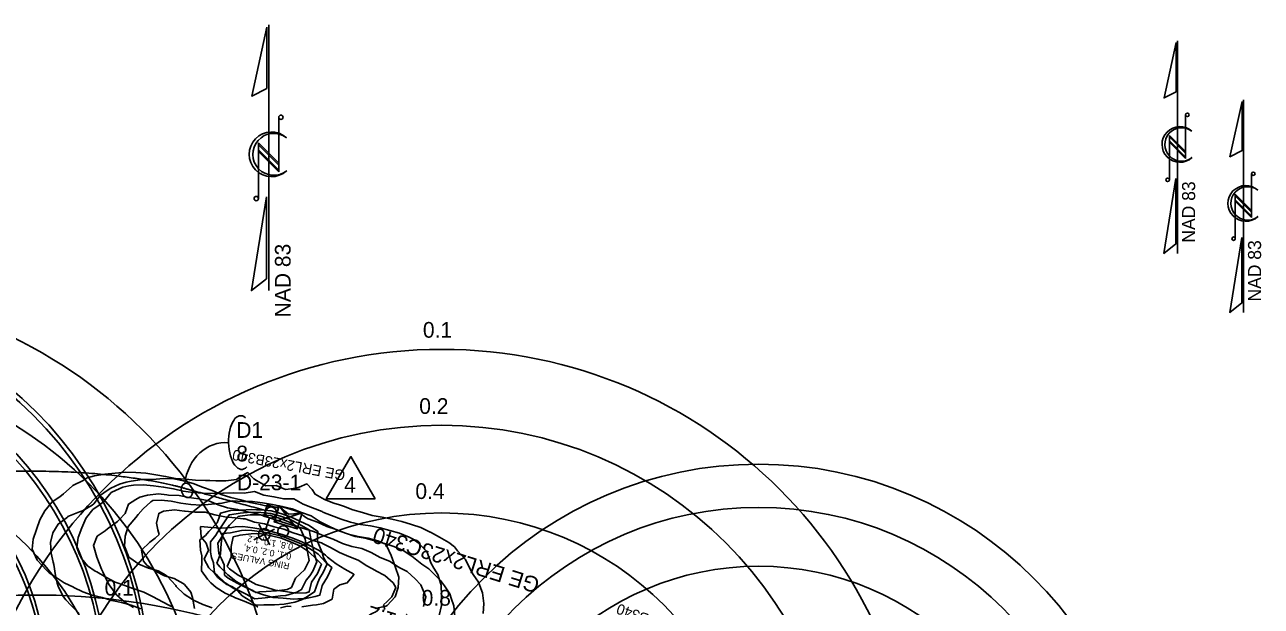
# Model space of a CAD drawing. Extents: x 1638506 to 1658005, y 834807 to 846788.
# Drawn here: x 1641220 to 1642165, y 842638 to 843083 of the extents above; entities that cross this region are included whole.
import ezdxf

# ---------------------------------------------------------------- set-up
doc = ezdxf.new("R2010")
doc.units = 0
for name, color, linetype in [('Default', 7, 'Continuous'), ('Old_Level_1', 7, 'Continuous'), ('Old_Level_2', 7, 'Continuous'), ('Old_Level_4', 7, 'Continuous'), ('Scratch_Level_0', 7, 'Continuous'), ('Sheet North Arrow CELL', 7, 'Continuous')]:
    doc.layers.add(name, color=color, linetype=linetype)

msp = doc.modelspace()

# ---------------------------------------------------------------- linework, layer by layer
at = {"layer": 'Default'}
for p, q in [((1641428.42, 842697.5), (1641414.73, 842715.25)), ((1641407.25, 842706.1), (1641404.63, 842697.54)), ((1641432.21, 842709.89), (1641410.93, 842702.85)), ((1641411.2, 842697.47), (1641395.43, 842689.09)), ((1641407.53, 842685.39), (1641399.12, 842701.17)), ((1641403.32, 842693.26), (1641403.32, 842693.26)), ((1641407.31, 842695.4), (1641407.31, 842695.4))]:
    msp.add_line(p, q, dxfattribs=at)
for points in [[(1641488.06, 842720.59), (1641450.67, 842720.59), (1641469.5, 842752.86)], [(1641414.13, 842713.31), (1641411.53, 842704.79), (1641402.97, 842707.4), (1641405.58, 842715.93)], [(1641432.21, 842709.89), (1641414.73, 842715.25), (1641410.93, 842702.85), (1641428.42, 842697.5)], [(1641421.57, 842706.37), (1641410.93, 842702.85), (1641414.73, 842715.25)], [(1641421.57, 842706.37), (1641428.42, 842697.5), (1641432.21, 842709.89)]]:
    msp.add_lwpolyline(points, close=True, dxfattribs=at)
msp.add_circle((1641403.32, 842693.3), 4.47, dxfattribs=at)
for centre, major_axis, ratio, start_param, end_param in [((1641385.66, 842763.53), (-0.49, 20.52), 0.466223, 5.884886, 7.853982), ((1641372.31, 842728.96), (-3.78, -34.34), 0.862742, 3.141593, 4.712389), ((1641385.66, 842763.53), (-0.49, 20.52), 0.466223, 1.570796, 3.572354)]:
    msp.add_ellipse(centre, major_axis=major_axis, ratio=ratio, start_param=start_param, end_param=end_param, dxfattribs=at)
msp.add_ellipse((1641344.25, 842726.93), major_axis=(1.72, -5.4), ratio=0.730797, dxfattribs=at)
msp.add_open_spline([(1641118.5, 842733.75), (1641184.14, 842741.69), (1641261.51, 842741.69), (1641322.44, 842734.15), (1641359.07, 842723.88), (1641404.28, 842711.67)], degree=2, dxfattribs=at)
at = {"layer": 'Old_Level_1'}
for points in [[(1641570.58, 842632.92), (1641570.95, 842640.63), (1641569.9, 842648.61), (1641568.78, 842652.1), (1641567.04, 842656.93), (1641563, 842662.76), (1641561.18, 842665.82), (1641557.27, 842673.69), (1641556.89, 842674.41), (1641550.81, 842680.74), (1641548.72, 842683.73), (1641544.25, 842687.24), (1641537.23, 842691.32), (1641530.2, 842694.99), (1641530.14, 842695.02), (1641523.04, 842698.63), (1641515.7, 842700.99), (1641508.35, 842703.31), (1641500.89, 842705.05), (1641493.38, 842706.5), (1641485.84, 842707.77), (1641478.47, 842710.01), (1641471.08, 842712.06), (1641463.82, 842714.85), (1641460.81, 842715.82), (1641456.49, 842717.28), (1641449.23, 842720.05), (1641442.2, 842724.08), (1641439.91, 842727.53), (1641435.92, 842732.07), (1641429.99, 842729.39), (1641427.51, 842728.78), (1641419.52, 842727.65), (1641412.31, 842730.72), (1641404.48, 842730.47), (1641397.44, 842734.43), (1641395.35, 842735.9), (1641390.81, 842740.54), (1641385.44, 842737.77), (1641382.05, 842735.38), (1641374.04, 842734.18), (1641366.27, 842734.24), (1641361.71, 842734.44), (1641358.56, 842734.64), (1641350.78, 842734.67), (1641343.14, 842735.44), (1641335.47, 842736.03), (1641327.98, 842737.59), (1641320.45, 842738.96), (1641312.87, 842740.05), (1641305.18, 842740.55), (1641297.49, 842741.02), (1641289.56, 842740.24), (1641289.5, 842740.23), (1641281.61, 842739.36), (1641273.59, 842738.11), (1641268.15, 842736.46), (1641265.11, 842734.43), (1641257.15, 842730.74), (1641256.54, 842730.21), (1641250.04, 842724.3), (1641247.23, 842722.11), (1641241.35, 842718.15), (1641237.97, 842714.28), (1641235.66, 842711.43), (1641231.79, 842704.37), (1641229.33, 842697.05), (1641226.71, 842689.76), (1641226.02, 842682.11), (1641229.92, 842673.59)], [(1641536.84, 842631.47), (1641538.72, 842638.9), (1641538.72, 842646.69), (1641538.45, 842654.52), (1641538.24, 842655.28), (1641535.91, 842662.78), (1641532.77, 842667.57), (1641530.49, 842671.59), (1641527.77, 842679.88), (1641527.38, 842680.32), (1641520.86, 842687.02), (1641516.96, 842689.7), (1641513.88, 842691.31), (1641506.68, 842694.41), (1641499.28, 842696.45), (1641491.86, 842698.41), (1641484.35, 842699.83), (1641476.77, 842700.95), (1641469.31, 842702.67), (1641461.95, 842704.95), (1641454.7, 842707.75), (1641448.13, 842710.42), (1641447.48, 842710.78), (1641440.25, 842713.72), (1641432.98, 842716.46), (1641425.94, 842720.4), (1641418.16, 842720.43), (1641410.7, 842722.13), (1641403.12, 842723.26), (1641395.87, 842726.05), (1641387.87, 842724.94), (1641380.1, 842725.02), (1641372.3, 842724.91), (1641371.56, 842724.81), (1641364.48, 842724.7), (1641356.7, 842724.73), (1641349.02, 842725.28), (1641341.44, 842726.39), (1641333.98, 842728.09), (1641326.46, 842729.49), (1641318.84, 842730.36), (1641311.2, 842731.15), (1641303.36, 842730.87), (1641299.91, 842730.49), (1641295.31, 842729.41), (1641286.79, 842725.54), (1641286.27, 842725.27), (1641280.73, 842718.53), (1641277.15, 842715.62), (1641272.48, 842712.3), (1641267.58, 842706.15), (1641267.11, 842705.52), (1641264.02, 842698.32), (1641261.19, 842691.07), (1641260.25, 842683.46)], [(1641488.06, 842636.77), (1641496.2, 842638.63), (1641497.14, 842638.94), (1641503.39, 842645.54), (1641505.71, 842652.89), (1641506.08, 842660.61), (1641503.27, 842668.92), (1641502.41, 842671.72), (1641500.3, 842677.26), (1641497.01, 842684.36), (1641495.93, 842685.87), (1641489.99, 842688.42), (1641482.58, 842690.45), (1641475.04, 842691.73), (1641467.6, 842693.57), (1641460.28, 842696.01), (1641453.14, 842699.44), (1641446.02, 842702.99), (1641445.9, 842703.05), (1641439.1, 842707.61), (1641431.77, 842710.01), (1641424.53, 842712.87), (1641417.08, 842714.69), (1641409.6, 842716.27), (1641402.05, 842717.52), (1641394.45, 842718.53), (1641386.66, 842718.49), (1641378.96, 842718.92), (1641370.97, 842717.14), (1641370.83, 842717.12), (1641362.92, 842716.4), (1641355.02, 842715.79), (1641347.31, 842716.18), (1641339.71, 842717.16), (1641332.22, 842718.72), (1641324.58, 842719.51), (1641318.12, 842719.29), (1641316.57, 842718.28), (1641310.92, 842712.85), (1641306.94, 842708.46), (1641305.12, 842706.16), (1641299.48, 842699.44), (1641297.03, 842692.11), (1641296.52, 842684.42), (1641299.95, 842676)], [(1641354.67, 842681.28), (1641355.52, 842677.06), (1641355.74, 842673.29), (1641355.42, 842665.57), (1641359.95, 842659.18), (1641362.4, 842656.47), (1641366.54, 842652.87), (1641373.52, 842648.55), (1641380.35, 842645.32), (1641380.67, 842645.18), (1641387.94, 842642.44), (1641395.14, 842639.35), (1641402.97, 842639.61), (1641410.74, 842639.53), (1641411.08, 842639.54), (1641418.63, 842640.07), (1641426.69, 842641.56), (1641431.86, 842643.42), (1641435.13, 842645.05), (1641441.66, 842649.36), (1641444.17, 842656.67), (1641445.74, 842660.1), (1641448.07, 842663.73), (1641451.46, 842670.87), (1641448.66, 842675.65), (1641447.47, 842679.41), (1641443.94, 842687.85), (1641444, 842692.22), (1641444.18, 842695.59), (1641437.72, 842700.23), (1641430.54, 842703.47), (1641423.38, 842706.77), (1641419.48, 842708.02), (1641416.06, 842709.27), (1641408.67, 842711.34), (1641401.03, 842712.09), (1641397.39, 842712.17), (1641393.3, 842712.42), (1641385.43, 842711.95), (1641377.57, 842711.53), (1641369.86, 842709.56), (1641368.81, 842706.35), (1641367.28, 842702.26), (1641360.92, 842695.67), (1641358.44, 842692.6), (1641354.1, 842689.17), (1641354.67, 842681.28)], [(1641362.26, 842679.85), (1641363.06, 842675.76), (1641364.54, 842671.64), (1641365.24, 842663.72), (1641367.96, 842660.39), (1641374.75, 842655.14), (1641378.54, 842653.44), (1641381.87, 842651.6), (1641388.95, 842647.84), (1641396.03, 842644.07), (1641403.99, 842645.01), (1641411.95, 842645.95), (1641415.72, 842646.45), (1641419.86, 842646.66), (1641428.1, 842649.09), (1641431.85, 842651.21), (1641435.37, 842658.33), (1641438.25, 842661.63), (1641440.48, 842665.15), (1641443.41, 842672.39), (1641441.46, 842678.71), (1641441.1, 842680.6), (1641439.19, 842688.75), (1641437.5, 842696.85), (1641437.13, 842697.11), (1641430.09, 842701.09), (1641422.99, 842704.71), (1641415.7, 842707.32), (1641408.29, 842709.32), (1641400.66, 842710.15), (1641392.92, 842710.36), (1641384.98, 842709.57), (1641376.98, 842708.42), (1641376.54, 842708.3), (1641372.03, 842701.37), (1641367.29, 842694.48), (1641366.27, 842692.84), (1641362.16, 842687.66), (1641362.26, 842679.85)], [(1641368.65, 842678.65), (1641370.62, 842674.57), (1641372.61, 842670.12), (1641373, 842662.27), (1641375.63, 842659.82), (1641382.7, 842655.99), (1641389.85, 842652.62), (1641394.54, 842650.43), (1641396.95, 842649.01), (1641399.72, 842649.46), (1641404.88, 842649.79), (1641412.77, 842650.34), (1641420.74, 842651.34), (1641424.08, 842652.67), (1641427.3, 842659.84), (1641430.77, 842663.26), (1641434.09, 842666.35), (1641437.71, 842673.46), (1641436.11, 842681.54), (1641435.19, 842686.78), (1641434.52, 842689.62), (1641430.68, 842698.13), (1641429.65, 842698.72), (1641422.6, 842702.65), (1641415.37, 842705.59), (1641408, 842707.76), (1641400.34, 842708.41), (1641392.53, 842708.31), (1641384.54, 842707.2), (1641383.37, 842707.02), (1641376.7, 842700.49), (1641375.04, 842698.09), (1641372.28, 842693.54), (1641367.86, 842686.59), (1641368.65, 842678.65)], [(1641260.25, 842683.46), (1641262.3, 842678.06), (1641263.62, 842675.04), (1641268.43, 842669.26), (1641274.21, 842665.27), (1641275.35, 842664.63), (1641282.38, 842660.66), (1641289.45, 842656.84), (1641296.74, 842654.23), (1641303, 842652.07), (1641304.05, 842651.68), (1641311.35, 842649.12), (1641318.47, 842645.56), (1641325.53, 842641.72), (1641331.06, 842639.01), (1641332.64, 842638.12)], [(1641229.92, 842673.59), (1641230.26, 842673.21), (1641236.73, 842666.23), (1641239.01, 842664.1), (1641243.5, 842660.82), (1641250.45, 842656.42), (1641257.59, 842652.96), (1641257.99, 842652.75), (1641264.72, 842649.48), (1641272, 842646.85), (1641279.46, 842645.09), (1641286.84, 842642.96), (1641294.32, 842641.35), (1641301.7, 842639.16), (1641308.99, 842636.54)], [(1641299.95, 842676), (1641300.72, 842675.37), (1641307.62, 842670.68), (1641314.82, 842667.58), (1641322.2, 842665.43), (1641326.49, 842663.22), (1641329.22, 842661.37), (1641335.67, 842654.28), (1641336.09, 842653.64), (1641342.23, 842647.77), (1641348.63, 842643.5), (1641349.16, 842643.22), (1641356.29, 842639.72), (1641363.61, 842637.25)]]:
    msp.add_lwpolyline(points, dxfattribs=at)
for centre, radius in [((1641016.92, 842574.38), 297), ((1641016.92, 842574.38), 264), ((1641016.92, 842574.38), 219), ((1641408.43, 842710.09), 4.21)]:
    msp.add_circle(centre, radius, dxfattribs=at)
at = {"layer": 'Old_Level_2'}
msp.add_arc((1641228.74, 842129.06), 518, 64.83812, 98.96792, dxfattribs=at)
at = {"layer": 'Old_Level_4'}
for centre, radius in [((1641051.91, 842515.45), 365), ((1641538.84, 842469.72), 365), ((1641051.91, 842515.45), 307), ((1641538.84, 842469.72), 307), ((1641051.91, 842515.45), 240), ((1641538.84, 842469.72), 240)]:
    msp.add_circle(centre, radius, dxfattribs=at)
at = {"layer": 'Scratch_Level_0'}
for points in [[(1641548.87, 842630.67), (1641548.24, 842638.89), (1641546.17, 842644.74), (1641545.02, 842647.91), (1641541.09, 842654.11), (1641537.9, 842658.14), (1641535.22, 842660.99), (1641529.06, 842666.93), (1641523.68, 842670.6), (1641522.48, 842671.52), (1641516.1, 842676.73), (1641509.42, 842681.01), (1641502.4, 842684.21), (1641495.1, 842686.5), (1641487.68, 842688.4), (1641480.31, 842690.44), (1641472.71, 842691.77), (1641465.47, 842694.25), (1641458.33, 842697.06), (1641451.05, 842699.42), (1641444.04, 842702.62), (1641436.85, 842705.26), (1641435.15, 842706.27), (1641430.29, 842709.94), (1641425.95, 842709.15), (1641421.94, 842708.85), (1641418.81, 842711.37), (1641415.69, 842714.5), (1641409.61, 842714.25), (1641407.64, 842714.39), (1641400.22, 842716.31), (1641392.64, 842717.67), (1641385.31, 842719.87), (1641377.84, 842721.63), (1641370.48, 842723.71), (1641363.47, 842726.94), (1641356.25, 842729.46), (1641349.06, 842732.12), (1641341.76, 842734.4), (1641334.17, 842735.76), (1641326.24, 842736.04), (1641318.03, 842735.39), (1641316.52, 842735.31), (1641310, 842735.36), (1641301.56, 842733.98), (1641297.73, 842733.17), (1641292.82, 842731.66), (1641286.06, 842728.8), (1641283.3, 842726.85), (1641278.27, 842723.22), (1641273.08, 842716.82), (1641271.81, 842715.71), (1641264.56, 842711.47), (1641262.16, 842710.48), (1641253.35, 842706.96), (1641252.94, 842706.64), (1641245.98, 842701.25), (1641241.89, 842694.51), (1641239.98, 842687.09), (1641240.58, 842678.89)], [(1641524.94, 842638.15), (1641526.78, 842645.59), (1641524.31, 842651.71), (1641522.85, 842654.83), (1641518.7, 842659.41), (1641512.42, 842664.95), (1641506.83, 842667.85), (1641505.55, 842668.63), (1641498.87, 842672.89), (1641491.77, 842675.81), (1641484.9, 842679.49), (1641477.82, 842682.47), (1641470.29, 842684.04), (1641462.99, 842686.31), (1641456.01, 842689.64), (1641448.85, 842692.38), (1641441.77, 842695.36), (1641434.43, 842697.53), (1641427.07, 842699.62), (1641419.75, 842701.84), (1641412.47, 842704.18), (1641405.22, 842706.65), (1641397.96, 842709.04), (1641390.44, 842710.63), (1641382.99, 842712.45), (1641375.36, 842713.68), (1641368.06, 842715.97), (1641360.98, 842718.97), (1641353.46, 842720.55), (1641345.73, 842721.43), (1641338.22, 842723.07), (1641330.3, 842723.37), (1641328.8, 842723.46), (1641322.56, 842724.26), (1641314.24, 842723.28), (1641308.22, 842721.88), (1641305.25, 842720.14), (1641299.74, 842716.51), (1641297.01, 842709.35), (1641292.24, 842704.15), (1641291.13, 842703.17), (1641283.53, 842697.53), (1641281.74, 842696.19), (1641275.67, 842691.97), (1641272.82, 842684.85), (1641275.38, 842676.03)], [(1641495.31, 842635.85), (1641494.44, 842639.66), (1641497.28, 842642.15), (1641500.87, 842645.67), (1641503.76, 842652.78), (1641501.68, 842656.24), (1641495.48, 842662.05), (1641488.54, 842665.48), (1641488.21, 842665.65), (1641481.75, 842669.4), (1641475.09, 842673.74), (1641467.9, 842676.4), (1641460.84, 842679.43), (1641454.01, 842683.22), (1641448.32, 842686.13), (1641447.13, 842686.87), (1641439.78, 842689.01), (1641432.8, 842692.3), (1641425.48, 842694.53), (1641418.34, 842697.33), (1641410.88, 842699.09), (1641403.59, 842701.42), (1641395.97, 842702.69), (1641388.72, 842705.12), (1641387.31, 842705.19), (1641380.99, 842706.03), (1641373.21, 842706.8), (1641365.68, 842708.33), (1641358.26, 842710.24), (1641350.31, 842710.45), (1641342.86, 842711.06), (1641342.5, 842711.1), (1641334.83, 842712.23), (1641326.43, 842710.98), (1641322.75, 842709.32), (1641321.08, 842701.83), (1641322.03, 842696.89), (1641322.95, 842693.23), (1641320.06, 842690.59), (1641316.05, 842687.37), (1641309.45, 842681.42), (1641311.19, 842672.86)], [(1641354.76, 842699.33), (1641354.64, 842698.68), (1641355.21, 842691.17), (1641358.91, 842686.67), (1641360.82, 842681.4), (1641357.54, 842674.41), (1641361.05, 842667.88), (1641364.96, 842664.08), (1641367.27, 842662.12), (1641373.48, 842656.36), (1641380.15, 842652.06), (1641382.81, 842650.49), (1641386.41, 842646.43), (1641393.16, 842642.37), (1641398.3, 842637.64)], [(1641431.9, 842638.11), (1641440.29, 842639.31), (1641443.3, 842639.61), (1641448.68, 842640.5), (1641455.28, 842643.88), (1641456.57, 842651.49), (1641461.14, 842654.74), (1641466.74, 842656.33), (1641471.48, 842662.18), (1641471.76, 842662.78), (1641471.68, 842662.84), (1641464.88, 842666.71), (1641458.14, 842670.8), (1641451.7, 842675.84), (1641449.98, 842677.59), (1641445.35, 842681.16), (1641438.43, 842684.67), (1641431.47, 842688.04), (1641424.28, 842690.69), (1641417.09, 842693.32), (1641409.68, 842695.25), (1641402.26, 842697.16), (1641394.62, 842698.35), (1641386.93, 842699.4), (1641381.1, 842699.11), (1641378.68, 842698.65), (1641370.52, 842698.17), (1641362.65, 842698.64), (1641354.85, 842699.33), (1641354.76, 842699.33)], [(1641367.13, 842671.42), (1641369.31, 842668.65), (1641375.38, 842662.44), (1641379.18, 842659.64), (1641381.84, 842657.44), (1641388.67, 842653.66), (1641395.47, 842649.76), (1641402.71, 842647.29), (1641410.07, 842645.2), (1641417.88, 842644.54), (1641425.65, 842643.76), (1641429.08, 842644.05), (1641433.8, 842644.19), (1641442.33, 842645.84), (1641445.7, 842646.87), (1641447.58, 842654.3), (1641451.63, 842661.05), (1641455.06, 842667.99), (1641450.44, 842671.81), (1641444.4, 842678.13), (1641441.98, 842680.09), (1641437.77, 842682.56), (1641430.93, 842686.31), (1641423.81, 842689.17), (1641416.64, 842691.89), (1641409.2, 842693.74), (1641401.72, 842695.43), (1641393.96, 842696.25), (1641389.1, 842696.61), (1641385.99, 842696.38), (1641377.42, 842694.62), (1641371.45, 842694.11), (1641370.32, 842686.45), (1641369.81, 842678.59), (1641367.13, 842671.42)], [(1641375.1, 842668.93), (1641376.8, 842666.99), (1641383.34, 842662.25), (1641390.31, 842658.91), (1641397.16, 842655.18), (1641404.52, 842653.08), (1641411.76, 842650.62), (1641419.52, 842649.78), (1641427.15, 842648.56), (1641435.22, 842648.74), (1641437.72, 842649.36), (1641439.37, 842656.87), (1641444, 842663.43), (1641446.93, 842670.53), (1641443.28, 842674.54), (1641437.04, 842680.22), (1641433.63, 842682.7), (1641430.39, 842684.58), (1641423.33, 842687.66), (1641416.19, 842690.46), (1641408.73, 842692.22), (1641401.18, 842693.71), (1641397.45, 842694), (1641393.23, 842693.91), (1641384.86, 842692.79), (1641379.59, 842691.57), (1641377.95, 842684.06), (1641378.02, 842676.03), (1641375.1, 842668.93)], [(1641240.58, 842678.89), (1641242.2, 842672.23), (1641242.6, 842670.24), (1641243.76, 842661.87), (1641245.16, 842656.05), (1641246.04, 842653.14), (1641249.95, 842645.74), (1641251.74, 842643.34), (1641255.84, 842638.94), (1641261.98, 842632.93)], [(1641275.38, 842676.03), (1641275.41, 842675.94), (1641278.99, 842666.89), (1641279.91, 842664.69), (1641283.33, 842657.52), (1641284.85, 842654.83), (1641290.5, 842647.29), (1641290.53, 842647.26), (1641296.76, 842641.64), (1641303.44, 842637.39)], [(1641311.19, 842672.86), (1641313.59, 842669.86), (1641320.15, 842665.23), (1641327.05, 842661.65), (1641334.42, 842659.57), (1641341.27, 842655.85), (1641342.32, 842655.12), (1641347.19, 842649.15), (1641348.51, 842645.17), (1641349.92, 842636.72)], [(1641415.62, 842637.3), (1641420.89, 842638.59), (1641423.97, 842638.37)]]:
    msp.add_lwpolyline(points, dxfattribs=at)
for centre, radius in [((1641018.82, 842577.25), 297), ((1641018.82, 842577.25), 264), ((1641018.82, 842577.25), 219), ((1641780.93, 842450.01), 297), ((1641780.93, 842450.01), 264), ((1641417.82, 842695.66), 4.21), ((1641780.93, 842450.01), 219)]:
    msp.add_circle(centre, radius, dxfattribs=at)
at = {"layer": 'Sheet North Arrow CELL'}
for p, q in [((1641406.73, 842879.64), (1641406.73, 843082.77)), ((1642100.96, 842908), (1642100.96, 843070.5)), ((1642100.96, 842908), (1642100.96, 843070.5)), ((1642100.96, 842908), (1642100.96, 843070.5)), ((1642151.33, 842862.98), (1642151.33, 843025.48)), ((1642107.09, 843013.95), (1642107.09, 842980.6)), ((1642107.09, 843013.95), (1642107.09, 842980.6)), ((1642107.09, 843013.95), (1642107.09, 842980.6)), ((1641414.39, 843012.08), (1641414.39, 842970.39)), ((1641420.14, 842996.55), (1641420.35, 842996.39)), ((1642107.09, 842985.8), (1642094.66, 842998.22)), ((1642094.66, 842998.22), (1642094.66, 842964.32)), ((1642107.09, 842985.8), (1642094.66, 842998.22)), ((1642094.66, 842998.22), (1642094.66, 842964.32)), ((1642107.09, 842985.8), (1642094.66, 842998.22)), ((1642094.66, 842998.22), (1642094.66, 842964.32)), ((1642107.09, 842984.57), (1642094.66, 842997)), ((1642094.66, 842997), (1642094.66, 842993.95)), ((1642107.09, 842984.57), (1642094.66, 842997)), ((1642094.66, 842997), (1642094.66, 842993.95)), ((1642107.09, 842984.57), (1642094.66, 842997)), ((1642094.66, 842997), (1642094.66, 842993.95)), ((1642111.69, 843001.52), (1642111.86, 843001.4)), ((1642111.69, 843001.52), (1642111.86, 843001.4)), ((1642111.69, 843001.52), (1642111.86, 843001.4)), ((1641414.39, 842976.89), (1641398.85, 842992.42)), ((1641398.85, 842992.42), (1641398.85, 842950.05)), ((1641414.39, 842975.36), (1641398.85, 842990.89)), ((1641398.85, 842990.89), (1641398.85, 842987.08)), ((1641414.39, 842971.55), (1641398.85, 842987.08)), ((1641398.85, 842987.08), (1641414.39, 842971.55)), ((1641414.39, 842970.39), (1641398.85, 842985.92)), ((1642107.09, 842981.52), (1642094.66, 842993.95)), ((1642094.66, 842993.95), (1642107.09, 842981.52)), ((1642107.09, 842981.52), (1642094.66, 842993.95)), ((1642094.66, 842993.95), (1642107.09, 842981.52)), ((1642107.09, 842981.52), (1642094.66, 842993.95)), ((1642094.66, 842993.95), (1642107.09, 842981.52)), ((1642107.09, 842980.6), (1642094.66, 842993.02)), ((1642107.09, 842980.6), (1642094.66, 842993.02)), ((1642107.09, 842980.6), (1642094.66, 842993.02)), ((1641414.39, 842971.55), (1641414.39, 842975.36)), ((1642107.09, 842981.52), (1642107.09, 842984.57)), ((1642107.09, 842981.52), (1642107.09, 842984.57)), ((1642107.09, 842981.52), (1642107.09, 842984.57)), ((1642157.46, 842968.93), (1642157.46, 842935.58)), ((1642162.06, 842956.51), (1642162.23, 842956.38)), ((1642157.46, 842940.78), (1642145.03, 842953.21)), ((1642145.03, 842953.21), (1642145.03, 842919.31)), ((1642157.46, 842939.56), (1642145.03, 842951.98)), ((1642145.03, 842951.98), (1642145.03, 842948.93)), ((1642157.46, 842936.51), (1642145.03, 842948.93)), ((1642145.03, 842948.93), (1642157.46, 842936.51)), ((1642157.46, 842935.58), (1642145.03, 842948.01)), ((1642157.46, 842936.51), (1642157.46, 842939.56))]:
    msp.add_line(p, q, dxfattribs=at)
for points in [[(1641405.32, 843080.99), (1641393.73, 843028.24), (1641405.32, 843034.11)], [(1642099.84, 843069.07), (1642090.56, 843026.87), (1642099.84, 843031.57)], [(1642099.84, 843069.07), (1642090.56, 843026.87), (1642099.84, 843031.57)], [(1642099.84, 843069.07), (1642090.56, 843026.87), (1642099.84, 843031.57)], [(1642150.21, 843024.06), (1642140.93, 842981.86), (1642150.21, 842986.56)], [(1642099.64, 842965.25), (1642090.44, 842908), (1642099.64, 842915.25)], [(1642099.64, 842965.25), (1642090.44, 842908), (1642099.64, 842915.25)], [(1642099.64, 842965.25), (1642090.44, 842908), (1642099.64, 842915.25)], [(1641405.07, 842951.2), (1641393.57, 842879.64), (1641405.07, 842888.7)], [(1642150.01, 842920.23), (1642140.81, 842862.98), (1642150.01, 842870.23)]]:
    msp.add_lwpolyline(points, close=True, dxfattribs=at)
for centre, radius in [((1641416.04, 843012.05), 1.66), ((1642108.41, 843013.92), 1.32), ((1642108.41, 843013.92), 1.32), ((1642108.41, 843013.92), 1.32), ((1642158.78, 842968.91), 1.32), ((1642093.34, 842964.27), 1.32), ((1642093.34, 842964.27), 1.32), ((1642093.34, 842964.27), 1.32), ((1641397.2, 842949.98), 1.66), ((1642143.71, 842919.26), 1.32)]:
    msp.add_circle(centre, radius, dxfattribs=at)
for centre, radius, start, end in [((1642102.69, 842991.28), 13.65, 47.84002, 312.39406), ((1642102.69, 842991.28), 13.65, 47.84002, 312.39406), ((1642102.69, 842991.28), 13.65, 47.84002, 312.39406), ((1642104.01, 842991.28), 12.8, 53.09504, 308.62871), ((1642104.01, 842991.28), 12.8, 53.09504, 308.62871), ((1642104.01, 842991.28), 12.8, 53.09504, 308.62871), ((1641408.89, 842983.74), 17.06, 47.84002, 312.39406), ((1641410.54, 842983.75), 15.99, 53.09504, 308.62871), ((1642153.06, 842946.26), 13.65, 47.84002, 312.39406), ((1642154.38, 842946.27), 12.8, 53.09504, 308.62871)]:
    msp.add_arc(centre, radius, start, end, dxfattribs=at)

# ---------------------------------------------------------------- texts
at = {"layer": 'Default'}
for s, p in [('D1', (1641381.95, 842767.12)), ('8', (1641381.95, 842749.12)), ('D-23-1', (1641382.49, 842727.09)), ('4', (1641464.32, 842725.2))]:
    msp.add_text(s, height=12, dxfattribs=at).set_placement(p)
at = {"layer": 'Old_Level_1'}
for s, height, rotation, p in [('GE ERL2x23B340', 8, 169.35554, (1641465.74, 842742.08)), ('0.8, 1.0, 1.2', 5, 169.35554, (1641425.73, 842686.13)), ('0.1, 0.2, 0.4,', 5, 169.35554, (1641424.35, 842678.76)), ('RING VALUES', 5, 169.35554, (1641422.96, 842671.39)), ('GE ERL2x23B340', 8, 160, (1641756.4, 842610.8))]:
    msp.add_text(s, height=height, rotation=rotation, dxfattribs=at).set_placement(p)
msp.add_text('0.1', height=12, dxfattribs=at).set_placement((1641281.35, 842646.63))
at = {"layer": 'Old_Level_4'}
for s, p in [('0.1', (1641524.5, 842843.64)), ('0.2', (1641521.7, 842785.42)), ('0.4', (1641518.75, 842720.41)), ('0.8', (1641523.55, 842638.91))]:
    msp.add_text(s, height=12, dxfattribs=at).set_placement(p)
at = {"layer": 'Scratch_Level_0'}
for s, p in [('GE ERL2x23C340', (1641614.62, 842659.56)), ('0.8, 1.0, 1.2', (1641564.76, 842613.93))]:
    msp.add_text(s, height=12, rotation=162.65246, dxfattribs=at).set_placement(p)
at = {"layer": 'Sheet North Arrow CELL'}
for height, p in [(10, (1642114.34, 842916.27)), (10, (1642114.34, 842916.27)), (10, (1642114.34, 842916.27)), (12, (1641423.45, 842859.22)), (10, (1642164.71, 842871.26))]:
    msp.add_text('NAD 83', height=height, rotation=90, dxfattribs=at).set_placement(p)

doc.saveas('drawing.dxf')
